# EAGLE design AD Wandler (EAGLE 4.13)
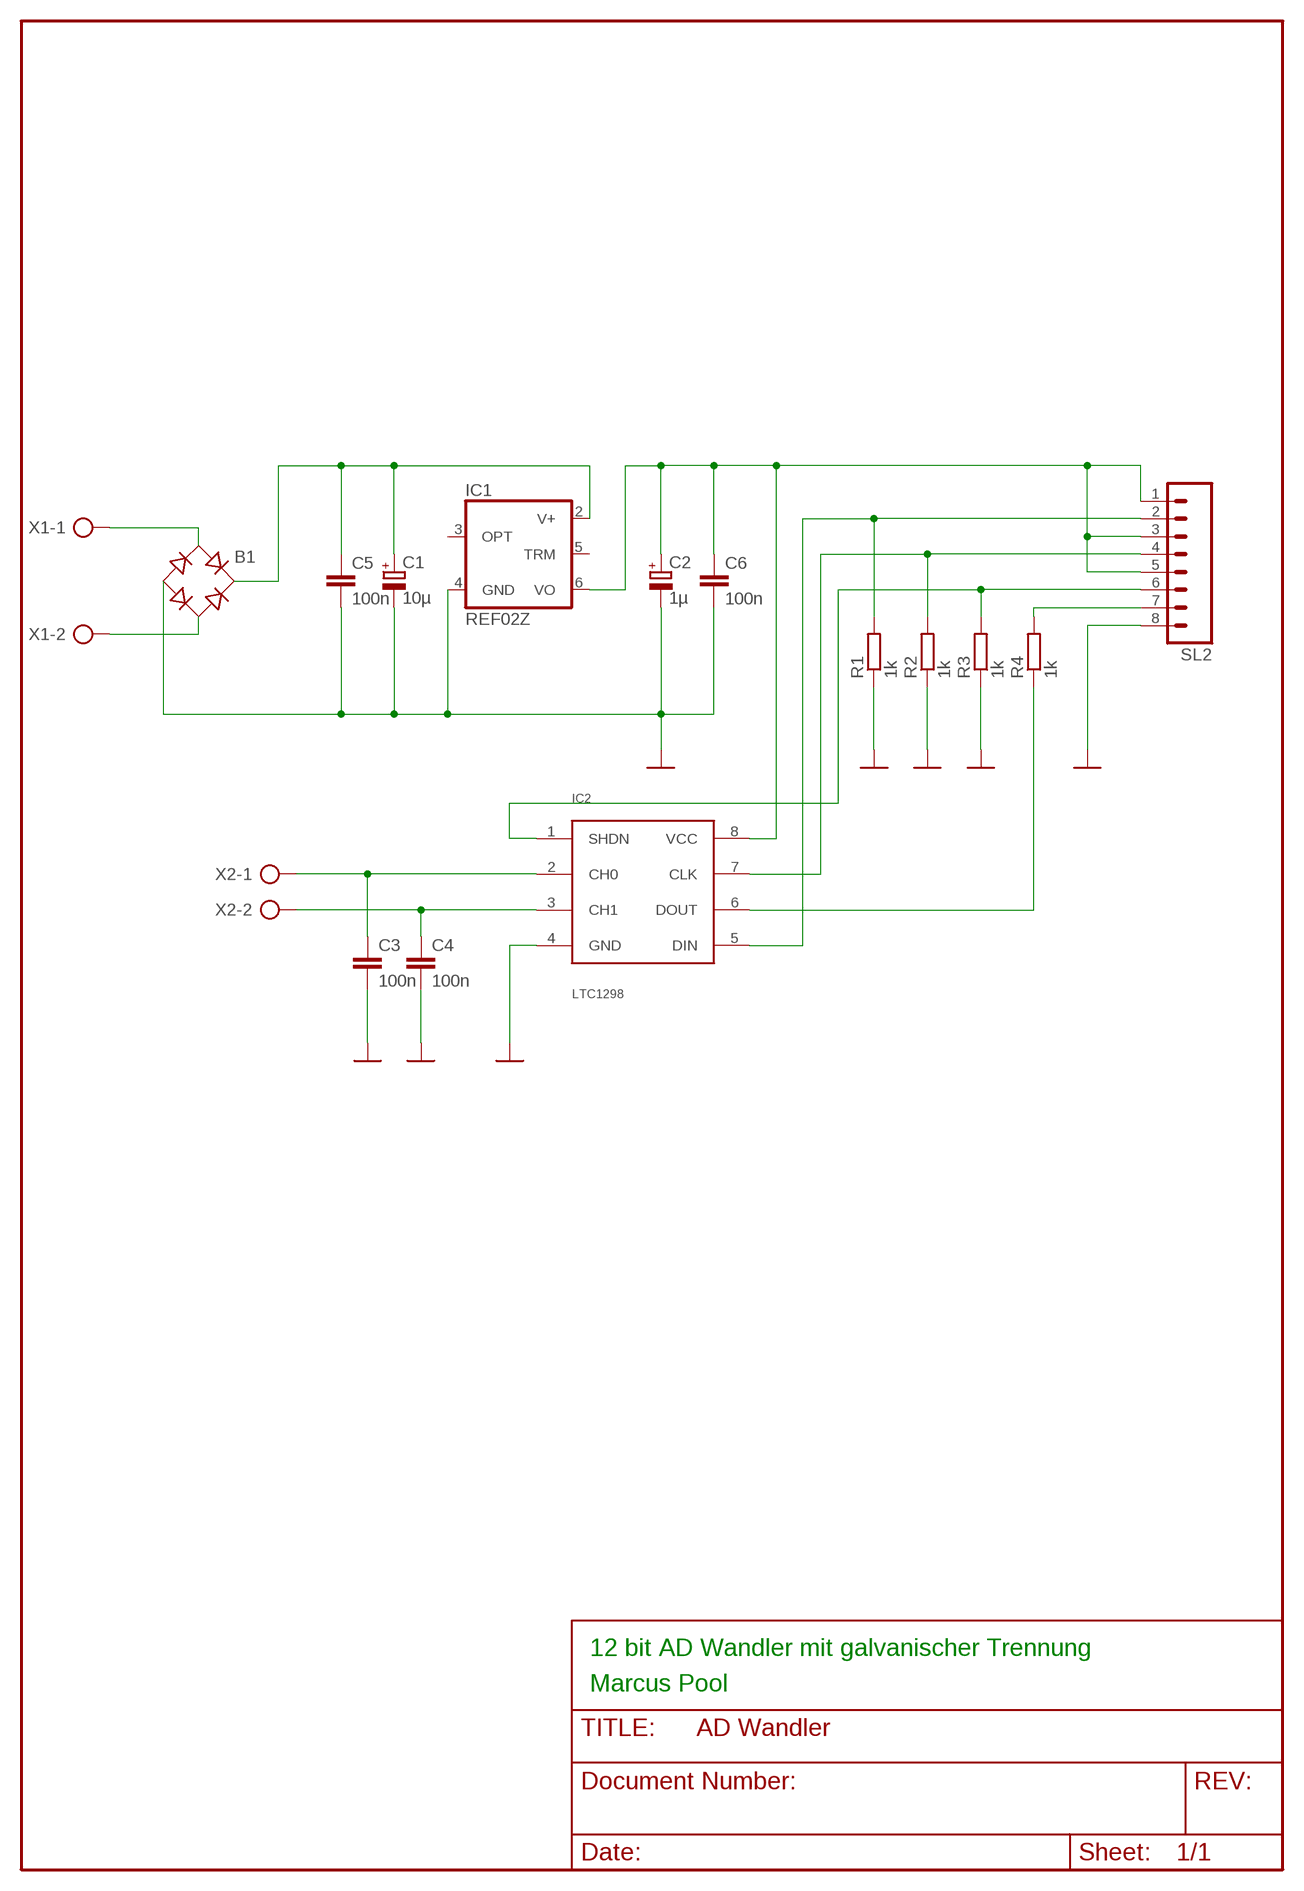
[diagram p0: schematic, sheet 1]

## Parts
B1  B-DIL  [B-DIL]
C1  10µ  CPOL-EUE2,5-6E  [E2,5-6E]
C2  1µ  CPOL-EUE2,5-6E  [E2,5-6E]
C3  100n  C-EU050-035X075  [C050-035X075]
C4  100n  C-EU050-035X075  [C050-035X075]
C5  100n  C-EU050-035X075  [C050-035X075]
C6  100n  C-EU050-035X075  [C050-035X075]
IC1  REF02Z  [DIL08]
IC2  LTC1298  [SOIC8]
R1  1k  R-EU_0207/10  [0207/10]
R2  1k  R-EU_0207/10  [0207/10]
R3  1k  R-EU_0207/10  [0207/10]
R4  1k  R-EU_0207/10  [0207/10]
SL2  M08  [08P]
X1  AK500/2  [AK500/2]
X2  AK500/2  [AK500/2]

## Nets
GND: B1.- C1.- C2.- C3.2 C4.2 C5.2 C6.2 IC1.4(GND) IC2.4(GND) R1.1 R2.1 R3.1 SL2.8 ; supply symbol labelled 
N$1: B1.+ C1.+ C5.1 IC1.2(V+)
N$2: R4.2 SL2.7
N$3: IC2.5(DIN) R1.2 SL2.2
N$4: IC2.7(CLK) R2.2 SL2.4
N$5: IC2.1(SHDN) R3.2 SL2.6
N$6: B1.AC2 X1.2
N$7: B1.AC1 X1.1
N$8: IC2.6(DOUT) R4.1
N$9: C3.1 IC2.2(CH0) X2.1
N$10: C4.1 IC2.3(CH1) X2.2
REF2: C2.+ C6.1 IC1.6(VO) IC2.8(VCC) SL2.1 SL2.3 SL2.5
Unconnected: IC1.3(OPT) IC1.5(TRM)

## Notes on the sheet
- 12 bit AD Wandler mit galvanischer Trennung
- Marcus Pool

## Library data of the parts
B1 = rectifier:B-DIL: RECTIFIER
C1 C2 = rcl:CPOL-EU: POLARIZED CAPACITOR, European symbol
C3-C6 = rcl:C-EU: CAPACITOR, European symbol
IC1 = linear:REF02: VOLTAGE REFERENCE
IC2 = linear-technology:LTC1298
R1-R4 = rcl:R-EU_: RESISTOR, European symbol
SL2 = con-amp-quick:M08: AMP QUICK CONNECTOR
X1 X2 = con-ptr500:AK500/2: CONNECTOR

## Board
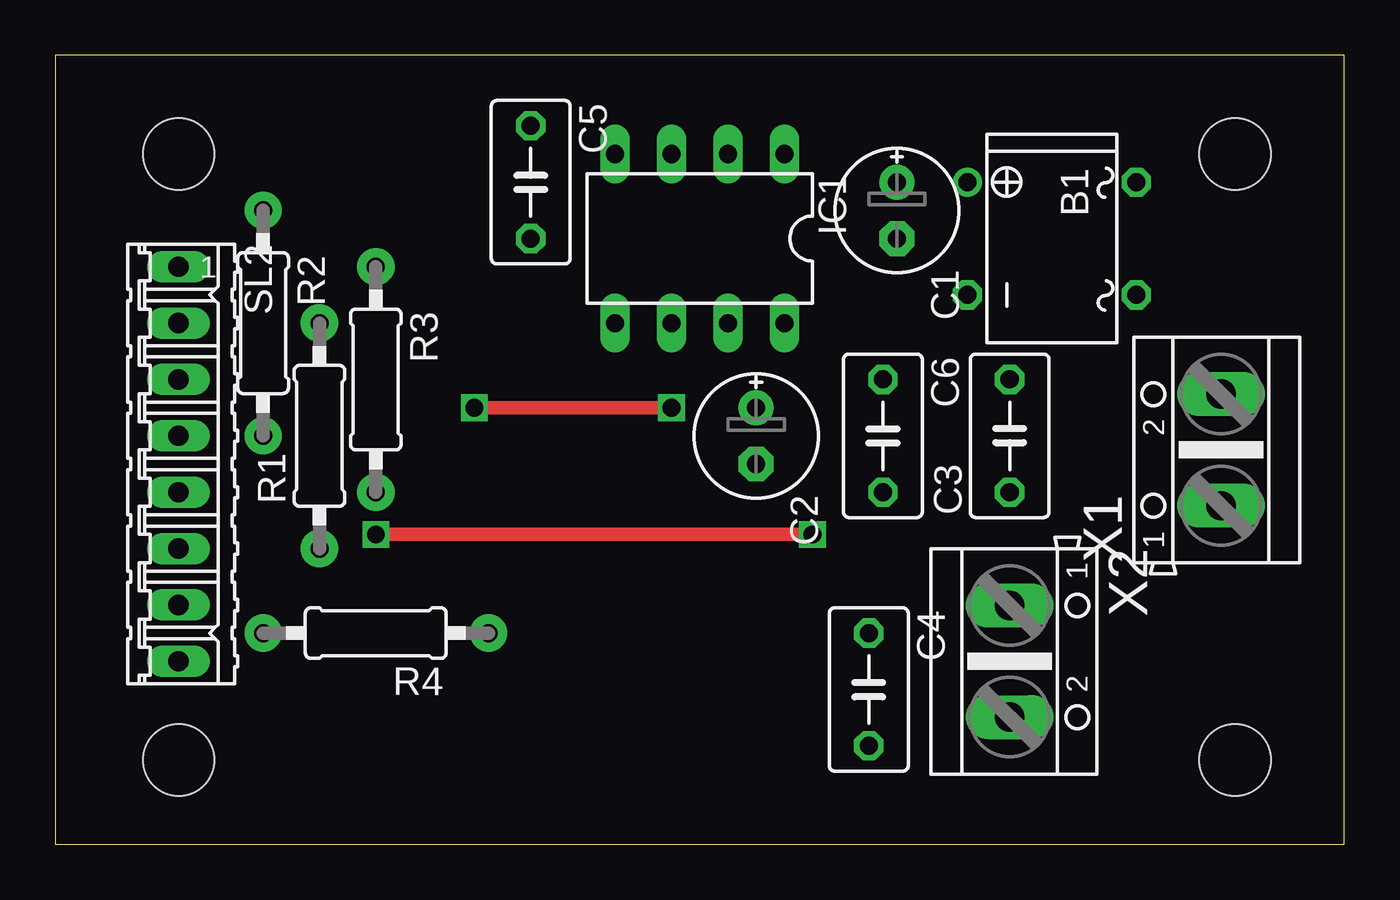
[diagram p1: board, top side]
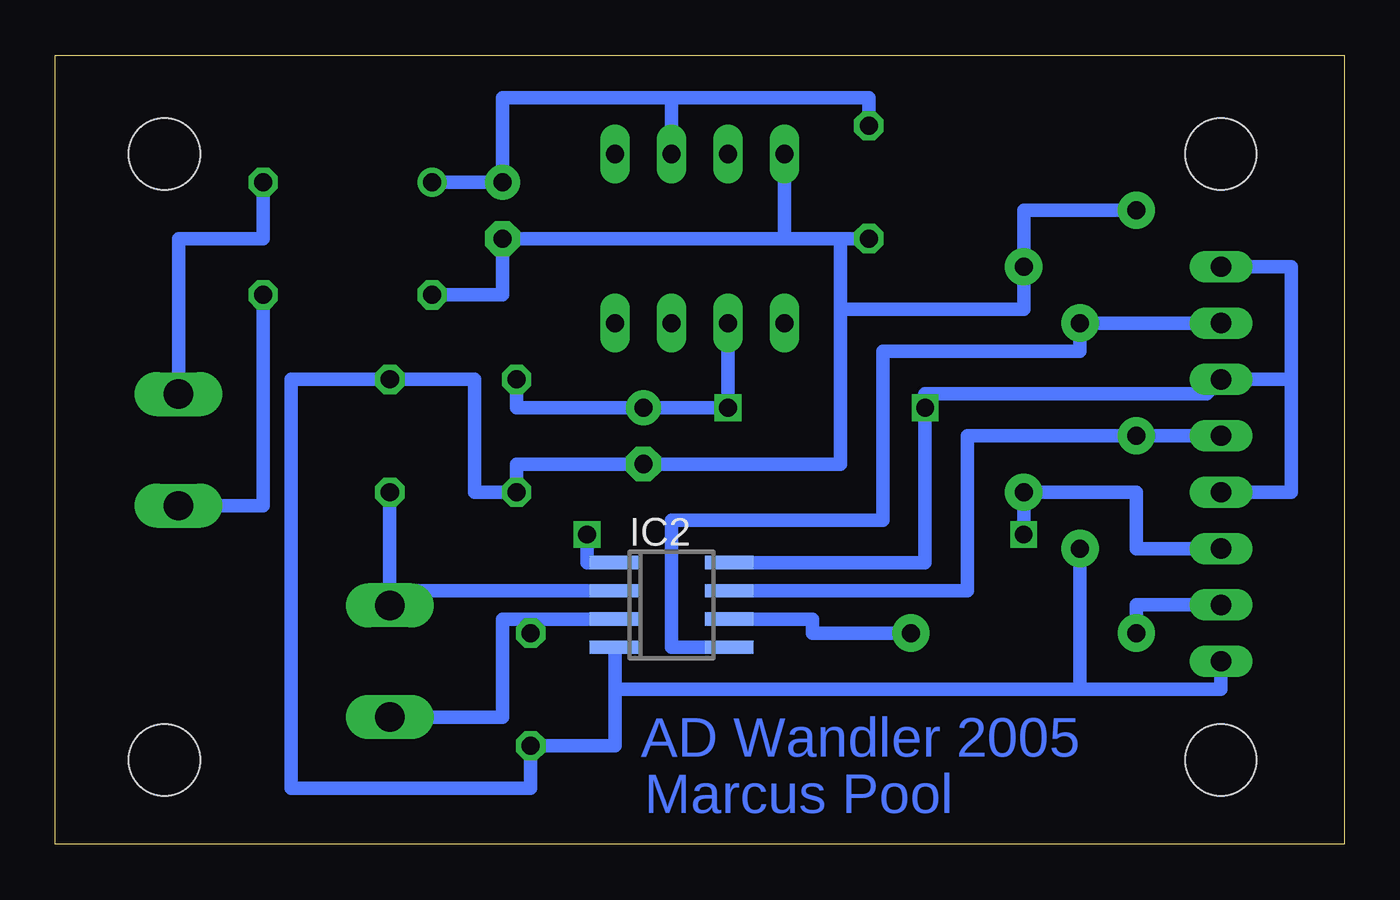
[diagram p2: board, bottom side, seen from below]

Size 58.09 x 35.55 mm. Coordinates in mm from the lower left corner, seen from the top.
Outline: 0,0 58.09,0 58.09,35.55 0,35.55 0,0
Copper layers (1*16): Top 0.035mm / dielectric 1.5mm / Bottom 0.035mm
Design rules "default": minimum track width 10mil, minimum drill 24mil, track to track 8mil, track to pad 8mil, pad to pad 8mil, via to via 8mil, smd to smd 8mil, copper to edge 40mil, drill to drill 8mil, minimum pad ring 10mil, minimum via ring 8mil, stop-mask expansion 4mil, vias tented up to drill 0mil, thermal gap 10mil
Holes 3.2 mm at 5.55,31.11 5.55,3.8 53.17,3.8 53.17,31.11

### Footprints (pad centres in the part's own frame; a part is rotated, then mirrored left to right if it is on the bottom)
B-DIL = drill 0.813 round: + -2.54,-3.81 | drill 0.813 octagon: - 2.54,-3.81; AC1 2.54,3.81; AC2 -2.54,3.81
E2,5-6E = drill 0.813 pad 1.575 round: + -1.27,0 | drill 0.813 pad 1.575 octagon: - 1.27,0
C050-035X075 = drill 0.813 octagon: 1 -2.54,0; 2 2.54,0
DIL08 = drill 0.813 long: 1 -3.81,-3.81; 2 -1.27,-3.81; 3 1.27,-3.81; 4 3.81,-3.81; 5 3.81,3.81; 6 1.27,3.81; 7 -1.27,3.81; 8 -3.81,3.81
SOIC8 = smd 0.6 x 2.2: 1 -1.905,-2.6; 2 -0.635,-2.6; 3 0.635,-2.6; 4 1.905,-2.6; 5 1.905,2.6; 6 0.635,2.6; 7 -0.635,2.6; 8 -1.905,2.6
0207/10 = drill 0.813 pad 1.676 round: 1 -5.08,0; 2 5.08,0
08P = drill 0.914 long: 1 -8.89,0; 2 -6.35,0; 3 -3.81,0; 4 -1.27,0; 5 1.27,0; 6 3.81,0; 7 6.35,0; 8 8.89,0
AK500/2 = drill 1.321 long: 1 -2.515,0; 2 2.515,0

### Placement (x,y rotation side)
B1  44.92,27.3 270 top
C1  37.94,28.57 270 top
C2  31.58,18.41 270 top
C3  43.02,18.41 90 top
C4  36.66,6.98 270 top
C5  21.42,29.84 270 top
C6  37.3,18.41 270 top
IC1  29.04,27.3 180 top
IC2  30.31,10.79 270 bottom
R1  11.9,18.41 90 top
R2  9.36,23.49 270 top
R3  14.44,20.95 270 top
R4  14.44,9.52 180 top
SL2  5.55,17.14 270 top
X1  52.54,17.77 90 top
X2  43.02,8.25 270 top

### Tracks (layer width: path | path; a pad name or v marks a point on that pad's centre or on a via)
GND
  Bottom 0.61: B1.- 37.94,24.76 C1.- 25.23,27.3 | 22.7,24.12 22.7,17.14 C2.- 37.3,17.14 C6.2 39.2,15.87 39.2,20.95 C3.2 47.46,20.95 47.46,2.54 36.66,2.54 C4.2 32.85,4.44 32.85,8.89 | SL2.8 5.55,6.98 11.9,6.98 | R2.1 14.44,28.57 R3.1 14.44,24.12 22.7,24.12 | 25.23,27.3 IC1.4 | 22.7,27.3 25.23,27.3 | 22.7,24.12 22.7,27.3 | 22.7,27.3 C5.2 | 32.85,8.89 IC2.4 | 11.9,6.98 R1.1 | 11.9,6.98 32.85,6.98 32.85,8.89
N$1
  Bottom 0.61: B1.+ C1.+ 37.94,33.65 30.31,33.65 | 30.31,33.65 IC1.2 | 30.31,33.65 21.42,33.65 C5.1
N$2
  Bottom 0.61: SL2.7 9.36,10.79 R4.2
N$3
  Bottom 0.61: SL2.2 R1.2 11.9,22.22 20.79,22.22 20.79,14.6 30.31,14.6 30.31,8.89 IC2.5
N$4
  Bottom 0.61: SL2.4 R2.2 16.98,18.41 16.98,11.43 IC2.7
N$5  (via drill 0.8)
  Top 0.61: v14.44,13.97 v34.12,13.97
  Bottom 0.61: SL2.6 9.36,13.33 9.36,15.87 R3.2 v14.44,13.97 | v34.12,13.97 34.12,12.7 IC2.1
N$6
  Bottom 0.61: B1.AC2 48.73,27.3 52.54,27.3 X1.2
N$7
  Bottom 0.61: X1.1 48.73,15.26 B1.AC1
N$8
  Bottom 0.61: IC2.6 23.96,10.16 23.96,9.52 R4.1
N$9
  Bottom 0.61: IC2.2 43.02,11.43 | 43.02,11.43 X2.1 | 43.02,11.43 C3.1
N$10
  Bottom 0.61: 37.94,5.74 X2.2 | 37.94,5.74 37.94,8.25 | IC2.3 37.94,10.16 | 37.94,10.16 37.94,5.74 | 37.94,10.16 36.66,10.16 C4.1
REF2  (via drill 0.8)
  Top 0.61: v18.88,19.68 v27.77,19.68
  Bottom 0.61: IC1.6 v27.77,19.68 C2.+ 37.3,19.68 C6.1 | SL2.1 2.38,26.03 2.38,20.95 | 2.38,20.95 2.38,15.87 SL2.5 | 2.38,20.95 SL2.3 6.18,20.31 18.88,20.31 v18.88,19.68 18.88,12.7 IC2.8 27.77,12.7

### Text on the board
Bottom: AD Wandler 2005 | Marcus Pool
